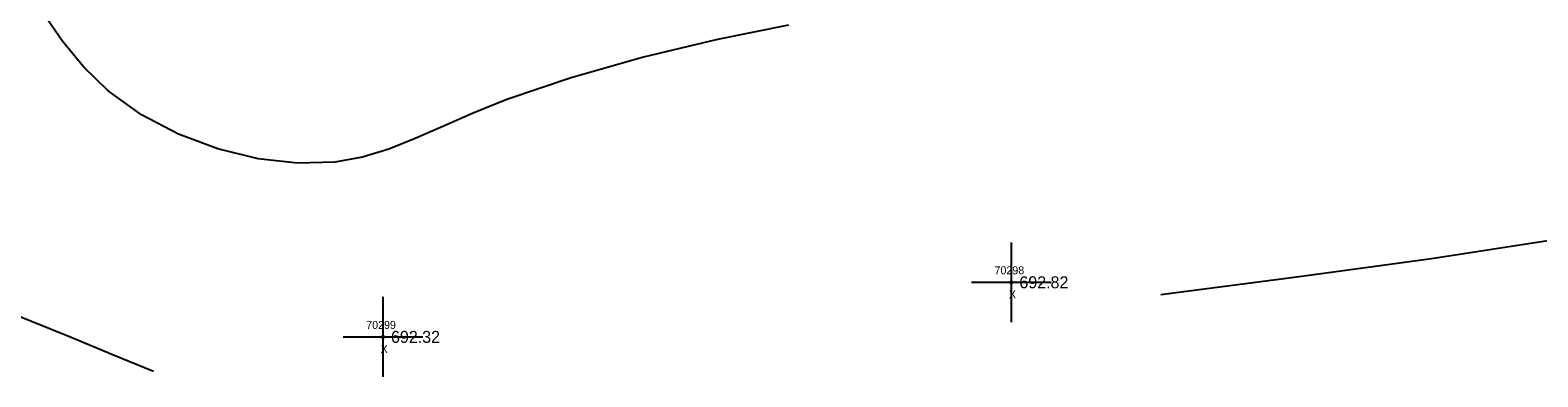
# Model space of a CAD drawing. Extents: x 1376587 to 1378239, y 1000335 to 1003031.
# Drawn here: x 1377155.3 to 1377344.2, y 1001471.1 to 1001514.5 of the extents above; entities that cross this region are included whole.
import ezdxf

# ---------------------------------------------------------------- set-up
doc = ezdxf.new("R2010")
doc.units = 0
for name, color, linetype in [('RD_DTM_Minor1', 7, 'Continuous'), ('RD_EX_Misc', 7, 'Continuous'), ('RD_EX_Misc_txCode', 7, 'Continuous'), ('RD_EX_TX_Misc_ELEV', 7, 'Continuous'), ('RD_SMD_Locator', 7, 'Continuous')]:
    doc.layers.add(name, color=color, linetype=linetype)

msp = doc.modelspace()

# ---------------------------------------------------------------- linework, layer by layer
at = {"layer": 'RD_DTM_Minor1'}
for points in [[(1377296.95, 1001481.4), (1377314.29, 1001483.64), (1377330.9, 1001485.9), (1377346.02, 1001488.23), (1377358.92, 1001490.64), (1377368.86, 1001493.17), (1377375.09, 1001495.83), (1377375.82, 1001496.37), (1377376.38, 1001496.93), (1377376.81, 1001497.51), (1377377.1, 1001498.13), (1377377.27, 1001498.78), (1377377.34, 1001499.49), (1377377.32, 1001500.07), (1377377.26, 1001500.68), (1377377.14, 1001501.35), (1377376.97, 1001502.06), (1377376.76, 1001502.83), (1377376.49, 1001503.65), (1377374.68, 1001508.37), (1377372.12, 1001514.05), (1377369.08, 1001520.22)], [(1377250.32, 1001515.12), (1377241.44, 1001513.32), (1377232.15, 1001511.09), (1377223.11, 1001508.54), (1377215.02, 1001505.8), (1377210.8, 1001504.09), (1377207.03, 1001502.43), (1377203.56, 1001500.91), (1377200.25, 1001499.6), (1377196.95, 1001498.59), (1377193.5, 1001497.97), (1377188.82, 1001497.83), (1377183.86, 1001498.38), (1377178.83, 1001499.61), (1377173.89, 1001501.46), (1377169.25, 1001503.9), (1377165.09, 1001506.9), (1377161.98, 1001509.9), (1377159.32, 1001513.15), (1377157.03, 1001516.51)], [(1377170.75, 1001471.73), (1377165.56, 1001473.88), (1377160.45, 1001475.99), (1377155.49, 1001478), (1377150.77, 1001479.88)]]:
    msp.add_lwpolyline(points, dxfattribs=at)
at = {"layer": 'RD_EX_Misc'}
for p, q in [((1377278.25, 1001477.92), (1377278.25, 1001487.92)), ((1377273.25, 1001482.92), (1377283.25, 1001482.92)), ((1377199.52, 1001471.08), (1377199.52, 1001481.08)), ((1377194.52, 1001476.08), (1377204.52, 1001476.08))]:
    msp.add_line(p, q, dxfattribs=at)
at = {"layer": 'RD_SMD_Locator'}
for centre in [(1377278.25, 1001482.92), (1377199.52, 1001476.08)]:
    msp.add_circle(centre, 0.15, dxfattribs=at)

# ---------------------------------------------------------------- texts
at = {"layer": 'RD_EX_Misc_txCode'}
for s, p in [('70298', (1377276.13, 1001483.92)), ('X', (1377277.93, 1001480.92)), ('70299', (1377197.41, 1001477.08)), ('X', (1377199.21, 1001474.08))]:
    msp.add_text(s, height=1, dxfattribs=at).set_placement(p)
at = {"layer": 'RD_EX_TX_Misc_ELEV'}
for s, p in [('692.82', (1377279.25, 1001482.17)), ('692.32', (1377200.52, 1001475.33))]:
    msp.add_text(s, height=1.5, dxfattribs=at).set_placement(p)

doc.saveas('drawing.dxf')
